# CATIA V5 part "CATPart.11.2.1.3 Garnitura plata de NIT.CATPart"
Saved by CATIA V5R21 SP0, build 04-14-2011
Part number: Garnitura plata de etanşare
Bounding box of the stored display mesh (mm): x -7 to 7, y -6.824 to 6.824, z 0 to 5
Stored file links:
  C:\Users\MIRCEA\Desktop\MOM\Mogan\model\CATPart.11.2.1.3 Garnitura plata de NIT.CATPart
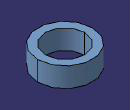
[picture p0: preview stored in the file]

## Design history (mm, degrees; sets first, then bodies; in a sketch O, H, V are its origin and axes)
Parameters
  Di = 10 mm
  De = 14 mm
  h = 3 mm
AxisSystem1: origin (0, 0, 0), X (1, 0, 0), Y (0, 1, 0), Z (0, 0, 1)
Body1 (main body)
  Sketch1 on xy-plane, origin (0, 0, 0), H (1, 0, 0), V (0, 1, 0)
    circle A1 centre (0, 0) radius 5
    circle A2 centre (0, 0) radius 7
    radius A1 = 5 {= Di/2}
    radius A2 = 7 {= De/2}
  Pad1: profile Sketch1, direction (0, 0, 1), length 5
